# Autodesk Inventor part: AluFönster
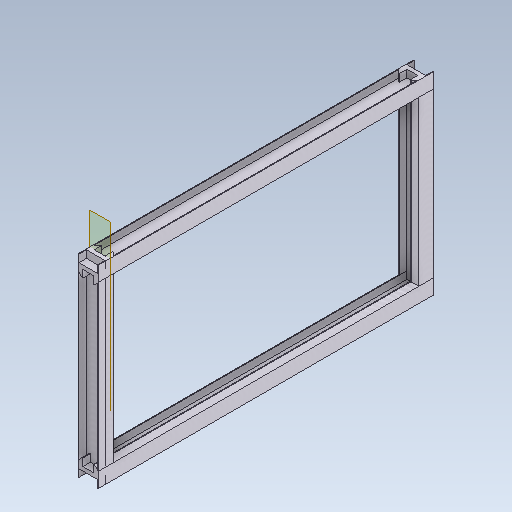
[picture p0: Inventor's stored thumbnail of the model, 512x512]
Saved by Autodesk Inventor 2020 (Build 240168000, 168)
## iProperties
Created: 2019-06
Part Number: AluFönster
Material: Aluminum 6061, Welded
Document SubType Name: Modeling
Designer: cl
Density: 2.7 g/cm^3
Appearance: Weld - Aluminum
Author: cl
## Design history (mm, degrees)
workplane "Work Plane5"
sketch "Sketch3"
  geometry: L1 (-48.6, -208.05)-(-48.6, -148.05) reference; L2 (-47.2, -209.45)-(-48.6, -208.05) reference; L3 (-47.2, -239.45)-(-47.2, -209.45) reference; L4 (-48.6, -240.85)-(-47.2, -239.45) reference; L5 (-48.6, -300.85)-(-48.6, -240.85) reference; L6 (1.4, -440)-(-48.6, -440) reference; L7 (1.4, -240.85)-(1.4, -300.85) reference; L8 (0, -239.45)-(1.4, -240.85) reference; L9 (0, -209.45)-(0, -239.45) reference; L10 (1.4, -208.05)-(0, -209.45) reference; L11 (1.4, -148.05)-(1.4, -208.05) reference; L12 (-47.2, 40)-(0, 40) reference; L13 (1.5, 168.75)-(-48.7, 168.75) reference; L14 (1.4, -65)-(3.4, -65); L15 (3.4, -65)-(3.4, -105); L16 (3.4, -105)-(-7.207, -115.607); L17 (-7.207, -115.607)-(-9.207, -115.607); L18 (-9.207, -115.607)-(-9.207, -95.607); L19 (-9.207, -95.607)-(-23.6, -95.607); L20 (-23.6, -62.341)-(-23.6, -107.316); L21 (-37.993, -95.607)-(-23.6, -95.607); L22 (-37.993, -115.607)-(-37.993, -95.607); L23 (-39.993, -115.607)-(-37.993, -115.607); L24 (-50.6, -105)-(-39.993, -115.607); L25 (-50.6, -65)-(-50.6, -105); L26 (-48.6, -65)-(-50.6, -65); L27 (181.964, -325)-(-287.514, -325); L28 (1.4, -529.25)-(-48.6, -529.25); L29 (-48.6, -393.65)-(-48.6, -333.65) reference; L30 (1.4, -333.65)-(1.4, -393.65) reference; L31 (3.4, -545)-(-7.207, -534.393); L32 (-9.207, -534.393)-(-9.207, -554.393); L33 (-7.207, -534.393)-(-9.207, -534.393); L34 (3.4, -585)-(3.4, -545); L35 (1.4, -565)-(1.4, -585); L36 (-28.6, -565)-(1.4, -565); L37 (-48.6, -565)-(-48.6, -585); L38 (1.4, -565)-(-48.6, -565); L39 (-28.6, -565)-(-48.6, -565); L40 (-48.6, -585)-(-50.6, -585); L41 (-50.6, -585)-(-50.6, -545); L42 (-50.6, -545)-(-39.993, -534.393); L43 (-39.993, -534.393)-(-37.993, -534.393); L44 (-37.993, -534.393)-(-37.993, -554.393); L45 (-37.993, -554.393)-(-23.6, -554.393); L46 (-9.207, -554.393)-(-23.6, -554.393); L47 (1.4, -585)-(3.4, -585); L48 (-48.6, -65)-(-48.6, -85); L49 (-48.6, -85)-(1.4, -85); L50 (1.4, -65)-(1.4, -85); L51 (-47.2, 38.95)-(-47.2, 40) reference; L52 (-48.6, 37.55)-(-47.2, 38.95) reference; L53 (-48.6, -22.45)-(-48.6, 37.55) reference; L54 (-47.2, -23.85)-(-48.6, -22.45) reference; L55 (-47.2, -53.85)-(-47.2, -23.85) reference; L56 (-48.6, -55.25)-(-47.2, -53.85) reference; L57 (-48.6, -115.25)-(-48.6, -55.25); L58 (-47.2, -116.65)-(-48.6, -115.25) reference; L59 (-47.2, -146.65)-(-47.2, -116.65) reference; L60 (-48.6, -148.05)-(-47.2, -146.65) reference; L61 (-47.2, -302.25)-(-48.6, -300.85) reference; L62 (-47.2, -332.25)-(-47.2, -302.25) reference; L63 (-48.6, -333.65)-(-47.2, -332.25) reference; L64 (-47.2, -395.05)-(-48.6, -393.65) reference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; 2 further points
  constraints: 74 end point, 19 symmetric about line, 8 perpendicular, 3 collinear, 3 vertical, 1 horizontal, 1 point on line
  dimensions: "d84" = 40 distance of L25.start L24.start; "d87" = 20 distance of L22.start L21.start; "d88" = 45 deg angle of L25 L24; "d89" = 2 distance of L23.start L22.start; "d90" = 15 distance of L24.start L23.start; "d121" = 20 distance of L26.start L48.end; "d124" = 20 distance between parallel lines of L40 L39; "d125" = 2 distance between parallel lines of L25 L48; "d127" = 253.75 distance between parallel lines of L49 L13 (derived); "d128" = 20 distance of L36.start L37.start; "d129" = 240 distance between parallel lines of L27 L49 (derived)
extrude "Extrusion3" new body sketch "Sketch3" distance "d55" = 870 (derived); taper "d57" = 0 deg; dims "d56" = 32, "d58" = 0
sketch "Sketch6"
  geometry: L1 (-8.607, 902)-(2, 902) reference; L2 (-52, 902)-(-41.393, 902) reference; L3 (-52, 902)-(-50, 902) reference; L4 (-52, 902)-(-52, 862); L5 (-52, 902)-(-52, 0) reference; L6 (-52, 862)-(-41.393, 851.393); L7 (-41.393, 902)-(-41.393, 0) reference; L8 (-41.393, 851.393)-(-39.393, 851.393); L9 (-39.393, 851.393)-(-39.393, 871.393); L10 (-39.393, 902)-(-39.393, 0) reference; L11 (-39.393, 871.393)-(-25, 871.393); L12 (-52, 902)-(-50, 902); L13 (-50, 902)-(-52, 902) reference; L14 (-50, 902)-(-50, 882); L15 (-50, 902)-(-50, 0) reference; L16 (-50, 882)-(-25, 882); L17 (-25, 871.393)-(-25, 991.393); L18 (0, 882)-(-25, 882); L19 (-10.607, 871.393)-(-25, 871.393); L20 (-10.607, 902)-(-10.606, 0); L21 (-10.607, 851.393)-(-10.607, 871.393); L22 (-8.607, 851.393)-(-10.607, 851.393); L23 (2, 862)-(-8.607, 851.393); L24 (2, 902)-(2, 862); L25 (2, 902)-(-8.607, 902); L26 (0, 902)-(0, 0); L27 (2, 902)-(0, 902); L28 (0, 902)-(0, 0); L29 (0, 902)-(0, 882); L30 (227.267, 451)-(-344.48, 451); L31 (-50, 20)-(-25, 20); L32 (-52, 0)-(-50, 0); L33 (-50, 0)-(-50, 902); L34 (-50, 0)-(-50, 20); L35 (-52, 0)-(-52, 40); L36 (-52, 40)-(-41.393, 50.607); L37 (-41.393, 50.607)-(-39.393, 50.607); L38 (-39.393, 50.607)-(-39.393, 30.607); L39 (-39.393, 30.607)-(-25, 30.607); L40 (-10.607, 30.607)-(-25, 30.607); L41 (-10.607, 0)-(-10.606, 902); L42 (-10.607, 50.607)-(-10.607, 30.607); L43 (2, 40)-(-8.607, 50.607); L44 (2, 0)-(2, 40); L45 (-8.607, 0)-(2, 0); L46 (2, 0)-(-8.607, 0); L47 (2, 0)-(0, 0); L48 (0, 0)-(0, 902); L49 (0, 0)-(0, 902); L50 (0, 20)-(-25, 20); L51 (0, 0)-(0, 20); L52 (-8.607, 0)-(2, 0); L53 (2, 0)-(-8.607, 0); L54 (2, 40)-(-8.607, 50.607); L55 (-8.607, 50.607)-(-10.607, 50.607); 2 further points
  constraints: 95 end point, 33 symmetric about line, 14 point on line, 2 horizontal, 2 perpendicular, 1 collinear
  dimensions: "d111" = 45 deg angle of L6 L4; "d112" = 2 distance of L6.end L8.end; "d114" = 20 distance of L3.end L14.end; "d117" = 27 distance from line of L17 L1.end; "d120" = 431 distance between parallel lines of L30 L16 (derived); "d131" = 120 distance of L11.end L17.end; "d132" = 40 distance of L44.start L43.start; "d133" = 20 distance of L42.start L40.start
extrude "Extrusion5" join sketch "Sketch6" distance "d118" = 520 (derived); taper "d119" = 0 deg
body "Solid3"
node "Reference7"
other parameters: "BladBredd" = 987.5, "Fönsterhöjd" = 862
